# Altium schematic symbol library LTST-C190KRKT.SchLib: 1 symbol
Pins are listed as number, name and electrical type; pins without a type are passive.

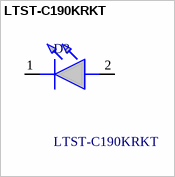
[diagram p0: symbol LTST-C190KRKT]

## LTST-C190KRKT
designator D?
LED,SMD,0603,Red,54mcd,130deg Lite-On LTST-C190KRKT Red LED, 631 nm, 1608 (0603), Rectangle Lens SMD Package; Geometry.Height: 0.8mm
footprint LEDC1608X80N
pins: 1 K, 2 A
